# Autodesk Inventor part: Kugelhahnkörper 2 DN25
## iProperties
Shininess: 64.0
Length Units: 11269
Angle Units: 11279
Time Units: 11290
Mass Units: 11283
Length Display Precision: 3
Angle Display Precision: 2
Compacted: True
Part Number: Kugelhahnkörper 2 DN25
Document SubType Name: Modeling
Created: 2004-08
Material: Messing (weiches, gelbes Messing)
Designer: AG
Manufacturer: Standard
Standards Organization: Custom
Density: 0.0
Volumn: 0.0
Area: 0.0
PropertySet Name: Model Information
Control State: 0
Master: False
Checked Out: False
Author: AG
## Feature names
1. Extrusion1
2. Drehung1 [Revolution]
3. Bohrung1 [Hole]
4. Drehung3 [Revolution]
5. Bohrung2 [Hole]
6. Drehung4 [Revolution]
7. Fase1 [Chamfer]
